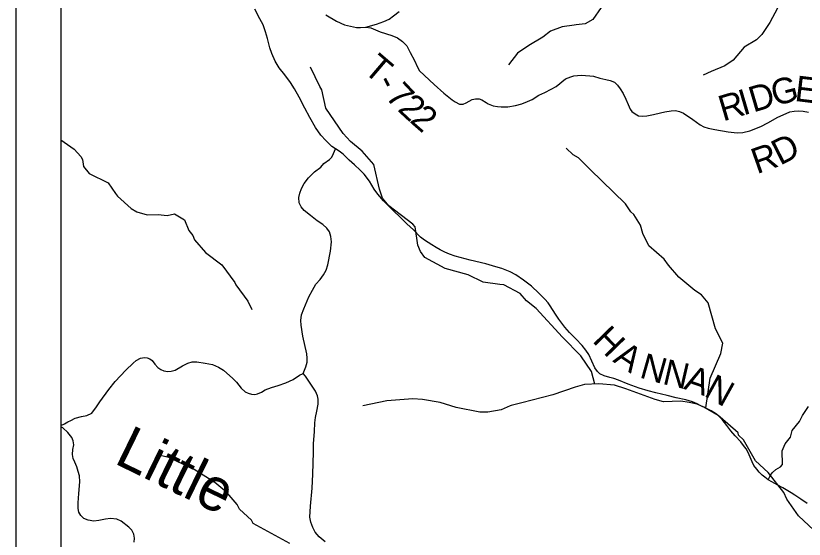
# Model space of a CAD drawing. Extents: x -1.8 to 75.7, y -2 to 25.
# Drawn here: x 2 to 3.751, y 17.804 to 18.965 of the extents above; entities that cross this region are included whole.
import ezdxf

# ---------------------------------------------------------------- set-up
doc = ezdxf.new("R2010")
doc.units = 0
for name, color, linetype in [('GM_X_County_Road', 7, 'Continuous'), ('GM_X_County_Road_Text', 7, 'Continuous'), ('GM_X_Minor_River', 7, 'Continuous'), ('GM_X_Minor_River_Text', 7, 'Continuous'), ('GM_X_Township', 7, 'Continuous'), ('GM_X_Township_Road', 7, 'Continuous'), ('GM_X_Township_Road_Text', 7, 'Continuous'), ('GM_X_Township_ROW', 7, 'Continuous'), ('SH_Data', 7, 'Continuous')]:
    doc.layers.add(name, color=color, linetype=linetype)

msp = doc.modelspace()

# ---------------------------------------------------------------- linework, layer by layer
at = {"layer": 'GM_X_County_Road'}
for points in [[(3.7576, 17.8828), (3.7429, 17.8927), (3.7296, 17.9015), (3.7215, 17.9065), (3.7147, 17.9108), (3.7034, 17.918), (3.6921, 17.9239), (3.6786, 17.9307), (3.6704, 17.9357), (3.663, 17.9413), (3.6571, 17.946), (3.6508, 17.9526), (3.6454, 17.9587), (3.639, 17.9675), (3.635, 17.9756), (3.6286, 17.9908), (3.6255, 17.9978), (3.6219, 18.0041), (3.6162, 18.0116), (3.6097, 18.0199), (3.5977, 18.0332), (3.588, 18.0445), (3.5792, 18.0561), (3.5688, 18.0692), (3.5604, 18.0771), (3.5539, 18.0823), (3.5442, 18.0884), (3.5326, 18.0942), (3.5213, 18.0999), (3.5128, 18.1044), (3.5024, 18.1087), (3.4875, 18.113), (3.4662, 18.1177), (3.4461, 18.1222), (3.4213, 18.1283), (3.4041, 18.1329), (3.384, 18.139), (3.3598, 18.148), (3.3384, 18.1566), (3.328, 18.1604), (3.3194, 18.1625), (3.3065, 18.1663), (3.2972, 18.1706), (3.2918, 18.1756), (3.286, 18.1837), (3.2789, 18.1991), (3.2724, 18.2133), (3.2661, 18.223), (3.2575, 18.2336), (3.2437, 18.2485), (3.2297, 18.2625), (3.2191, 18.2743), (3.2123, 18.2831), (3.2058, 18.2919), (3.1988, 18.3034), (3.1868, 18.3217), (3.1823, 18.3283), (3.175, 18.3366), (3.1615, 18.3497), (3.145, 18.3649), (3.1276, 18.3784), (3.1104, 18.3902), (3.0978, 18.3969), (3.079, 18.4044), (3.0662, 18.4082), (3.044, 18.4148), (3.009, 18.4231), (2.9756, 18.432), (2.9629, 18.4362), (2.9528, 18.4408), (2.9426, 18.4457), (2.9336, 18.4509), (2.9236, 18.4568), (2.9076, 18.4674), (2.8985, 18.4742), (2.8832, 18.4902), (2.8687, 18.5038), (2.8547, 18.517), (2.8375, 18.5336), (2.8168, 18.5544), (2.8043, 18.5693), (2.7959, 18.5803), (2.7854, 18.5981), (2.7735, 18.6138), (2.7645, 18.6229), (2.7518, 18.6345), (2.7406, 18.6446), (2.7268, 18.658), (2.7182, 18.6651), (2.7098, 18.67), (2.7019, 18.6754), (2.6888, 18.6881), (2.6771, 18.7006), (2.6653, 18.7174), (2.6526, 18.7397), (2.6418, 18.76), (2.6291, 18.7849), (2.619, 18.8028), (2.61, 18.817), (2.5971, 18.8342), (2.5848, 18.8499), (2.5758, 18.8648), (2.5685, 18.8816), (2.5641, 18.8938), (2.5588, 18.9147), (2.5547, 18.9295), (2.5491, 18.945), (2.5422, 18.9588), (2.5306, 18.9797)], [(2.6883, 18.9676), (2.712, 18.9536), (2.7302, 18.9451), (2.7432, 18.9418), (2.7569, 18.9395), (2.7654, 18.9392), (2.7775, 18.9401), (2.801, 18.9467), (2.8176, 18.9526), (2.8291, 18.9574), (2.8388, 18.9649), (2.8516, 18.9746)]]:
    msp.add_lwpolyline(points, dxfattribs=at)
at = {"layer": 'GM_X_Minor_River'}
for points in [[(3.4876, 19.2435), (3.4826, 19.241), (3.4682, 19.2168), (3.4642, 19.1831), (3.4509, 19.1668), (3.428, 19.1607), (3.4004, 19.1365), (3.3858, 19.1138), (3.3742, 19.1062), (3.3531, 19.0963), (3.3264, 19.0394), (3.3226, 19.0236), (3.318, 19.0108), (3.2812, 18.9573), (3.2647, 18.9472), (3.2446, 18.9448), (3.2396, 18.9442), (3.2131, 18.9404), (3.1875, 18.9314), (3.1704, 18.9175), (3.1389, 18.8995), (3.1138, 18.8821), (3.0941, 18.8561)], [(3.7086, 19.0147), (3.6745, 18.9504), (3.6567, 18.9237), (3.645, 18.9119), (3.6173, 18.8957), (3.5926, 18.8668), (3.5741, 18.8545), (3.5442, 18.8418), (3.5266, 18.8336)], [(3.2861, 18.1476), (3.2787, 18.1759), (3.2548, 18.2108), (3.2137, 18.252), (3.1552, 18.3158), (3.1337, 18.3328), (3.1203, 18.3492), (3.0834, 18.3682), (3.0747, 18.3689), (3.0375, 18.3742), (3.0043, 18.3905), (2.9537, 18.4042), (2.9083, 18.4289), (2.8985, 18.4421), (2.8929, 18.4559), (2.8866, 18.4968), (2.8815, 18.5026), (2.8283, 18.5434), (2.8144, 18.5602), (2.8075, 18.5802), (2.7948, 18.6349), (2.7692, 18.665), (2.7434, 18.6863), (2.7269, 18.7039), (2.6882, 18.7602), (2.6796, 18.8007), (2.6749, 18.8081), (2.6546, 18.8513)], [(2.1, 18.6899), (2.1295, 18.6689), (2.1445, 18.6532), (2.1485, 18.6462), (2.1503, 18.631), (2.163, 18.615), (2.2051, 18.5947), (2.2218, 18.5706), (2.2261, 18.5652), (2.2563, 18.5376), (2.2686, 18.5304), (2.2918, 18.5232), (2.316, 18.5239), (2.336, 18.5218), (2.3523, 18.5254), (2.375, 18.5122), (2.3845, 18.4887), (2.3928, 18.4774), (2.3971, 18.4678), (2.4212, 18.4401), (2.4574, 18.4123), (2.4864, 18.373), (2.4889, 18.368), (2.5151, 18.3322), (2.5242, 18.3133)], [(3.5325, 18.095), (3.5417, 18.1612), (3.5657, 18.2155), (3.5701, 18.2389), (3.5537, 18.2702), (3.5373, 18.328), (3.5227, 18.3463), (3.5079, 18.3552), (3.4725, 18.3848), (3.4495, 18.4121), (3.4397, 18.4253), (3.4058, 18.4549), (3.3927, 18.4819), (3.3872, 18.5007), (3.3724, 18.5239), (3.3661, 18.5298), (3.3542, 18.5477), (3.2752, 18.6242), (3.2496, 18.6501), (3.238, 18.6566), (3.2222, 18.6711)], [(3.7719, 17.8234), (3.7382, 17.8557), (3.7121, 17.8928), (3.7053, 17.9073), (3.6708, 17.9513), (3.6428, 17.9774), (3.6334, 17.993), (3.6159, 18.0241), (3.605, 18.0347), (3.6038, 18.0397), (3.5641, 18.0746), (3.5596, 18.078), (3.5282, 18.0969), (3.5134, 18.1033), (3.4956, 18.1067), (3.4767, 18.1097), (3.4386, 18.1088), (3.4197, 18.1137), (3.3546, 18.1372), (3.3293, 18.1455), (3.2945, 18.1488), (3.2627, 18.1468), (3.242, 18.1411), (3.1928, 18.1242), (3.1236, 18.1061)], [(3.1239, 18.1061), (3.1002, 18.1004), (3.0976, 18.0997), (3.0776, 18.0905), (3.0481, 18.0859), (3.0307, 18.0854), (2.9782, 18.0956), (2.9422, 18.1069), (2.9029, 18.1136), (2.8814, 18.1151), (2.8243, 18.1104), (2.7706, 18.0996)], [(2.6088, 17.7943), (2.5274, 17.8382), (2.5233, 17.8458), (2.4968, 17.8701), (2.4919, 17.8807), (2.4692, 17.9065), (2.4639, 17.9107), (2.4419, 17.9297), (2.3961, 17.9584), (2.3402, 17.9853), (2.3209, 17.9894), (2.3209, 17.9891)]]:
    msp.add_lwpolyline(points, dxfattribs=at)
at = {"layer": 'GM_X_Township'}
msp.add_lwpolyline([(6.4874, 20.9), (2.1, 20.9), (2.1, 17.3659)], dxfattribs=at)
at = {"layer": 'GM_X_Township_Road'}
for points in [[(2.7775, 18.9401), (2.7884, 18.9381), (2.8092, 18.9297), (2.8351, 18.9212), (2.8475, 18.9162), (2.8587, 18.908), (2.868, 18.8982), (2.8761, 18.8838), (2.8854, 18.8658), (2.8924, 18.8509), (2.8967, 18.8434), (2.929, 18.813), (2.9506, 18.7936), (2.9687, 18.7786), (2.9758, 18.7741), (2.9853, 18.7694), (2.9931, 18.7692), (3.0001, 18.7718), (3.0136, 18.7792), (3.0208, 18.781), (3.0288, 18.7807), (3.035, 18.7786), (3.0444, 18.773), (3.0493, 18.7698), (3.0602, 18.7656), (3.07, 18.7638), (3.0778, 18.7632), (3.0927, 18.7632), (3.1098, 18.7662), (3.1235, 18.7701), (3.1361, 18.7747), (3.1464, 18.7795), (3.1617, 18.7889), (3.1746, 18.7953), (3.1889, 18.8021), (3.1998, 18.8085), (3.2208, 18.8252), (3.2323, 18.8297), (3.2394, 18.8318), (3.2552, 18.8331), (3.2744, 18.832), (3.2827, 18.831), (3.2969, 18.8271), (3.3105, 18.8235), (3.3202, 18.8214), (3.3292, 18.8179), (3.336, 18.8115), (3.3424, 18.8034), (3.3486, 18.7925), (3.3544, 18.7805), (3.3599, 18.7686), (3.364, 18.7581), (3.3683, 18.7531), (3.3753, 18.7474), (3.383, 18.7435), (3.3907, 18.7425), (3.401, 18.7431), (3.416, 18.7465), (3.4316, 18.7499), (3.4416, 18.7523), (3.4555, 18.7542), (3.4647, 18.7547), (3.4739, 18.7531), (3.4829, 18.7489), (3.5034, 18.735), (3.5196, 18.7232), (3.5282, 18.7185), (3.5376, 18.7157), (3.5522, 18.7128), (3.5821, 18.708), (3.602, 18.7055), (3.6141, 18.7065), (3.6298, 18.7097), (3.6546, 18.7196), (3.6702, 18.7279), (3.6924, 18.7401), (3.7108, 18.7487), (3.7191, 18.7519), (3.7287, 18.7538), (3.7382, 18.754), (3.7482, 18.7532), (3.76, 18.751)], [(2.1, 18.056), (2.1079, 18.0595), (2.1154, 18.0644), (2.1221, 18.0672), (2.1316, 18.0722), (2.1462, 18.076), (2.1576, 18.0784), (2.1688, 18.0834), (2.1796, 18.0973), (2.1867, 18.1085), (2.2063, 18.1361), (2.2207, 18.1539), (2.2441, 18.1785), (2.2605, 18.1944), (2.2676, 18.2004), (2.2771, 18.2054), (2.2855, 18.2069), (2.2917, 18.206), (2.2979, 18.2039), (2.3027, 18.2), (2.3091, 18.1918), (2.3154, 18.1849), (2.322, 18.18), (2.3289, 18.1776), (2.338, 18.1759), (2.3451, 18.1763), (2.3543, 18.1785), (2.3705, 18.1882), (2.3819, 18.1946), (2.3918, 18.197), (2.4019, 18.1976), (2.4202, 18.1946), (2.4365, 18.1914), (2.4499, 18.1856), (2.4613, 18.1785), (2.4822, 18.1604), (2.4901, 18.152), (2.5007, 18.1389), (2.5095, 18.1307), (2.5157, 18.1277), (2.5235, 18.1253), (2.5308, 18.1249), (2.537, 18.126), (2.5454, 18.1296), (2.5538, 18.135), (2.568, 18.1402), (2.5827, 18.1447), (2.5999, 18.1505), (2.616, 18.1583), (2.63, 18.1675), (2.6384, 18.1714), (2.6438, 18.1858), (2.6468, 18.1966), (2.647, 18.2054), (2.6461, 18.2151), (2.6373, 18.2544), (2.6334, 18.2788), (2.6332, 18.2891), (2.6347, 18.3014), (2.6395, 18.3147), (2.6511, 18.3414), (2.6586, 18.356), (2.6662, 18.3698), (2.6756, 18.3803), (2.6832, 18.3902), (2.6892, 18.401), (2.6933, 18.4128), (2.6987, 18.443), (2.7008, 18.4632), (2.6997, 18.4755), (2.6965, 18.4856), (2.6909, 18.494), (2.6821, 18.5019), (2.6692, 18.5105), (2.6547, 18.5217), (2.6405, 18.5329), (2.6337, 18.5413), (2.6296, 18.5499), (2.6287, 18.5618), (2.6304, 18.5717), (2.6347, 18.582), (2.6403, 18.5927), (2.6502, 18.6054), (2.6634, 18.6186), (2.6771, 18.6295), (2.6844, 18.6371), (2.6963, 18.6465), (2.7019, 18.6515), (2.7058, 18.6599), (2.7098, 18.67)], [(2.6871, 17.7975), (2.6734, 17.8086), (2.6649, 17.8195), (2.6598, 17.8297), (2.6551, 17.8412), (2.6533, 17.8524), (2.6545, 17.8771), (2.658, 17.9168), (2.6594, 17.9482), (2.6612, 17.9966), (2.6614, 18.0156), (2.6631, 18.0429), (2.6642, 18.0621), (2.6659, 18.0739), (2.6687, 18.0877), (2.6713, 18.1034), (2.6717, 18.1143), (2.67, 18.1219), (2.6655, 18.1318), (2.6433, 18.1656), (2.6384, 18.1714)], [(2.2628, 17.797), (2.2635, 17.806), (2.2621, 17.8151), (2.2577, 17.8237), (2.2512, 17.8304), (2.2339, 17.8434), (2.2243, 17.8481), (2.2104, 17.8497), (2.1996, 17.8481), (2.1848, 17.8452), (2.1732, 17.8438), (2.1604, 17.8456), (2.151, 17.8499), (2.1443, 17.8562), (2.1398, 17.8635), (2.1384, 17.8718), (2.1382, 17.8844), (2.14, 17.9048), (2.1422, 17.9312), (2.1414, 17.9442), (2.1389, 17.9541), (2.1357, 17.9646), (2.1308, 17.9745), (2.1275, 17.983), (2.1257, 17.9915), (2.127, 18.0025), (2.129, 18.0133), (2.1277, 18.022), (2.1243, 18.0294), (2.1158, 18.0401), (2.1046, 18.0507), (2.1, 18.0531)]]:
    msp.add_lwpolyline(points, dxfattribs=at)
at = {"layer": 'GM_X_Township_ROW'}
msp.add_lwpolyline([(3.6704, 17.9357), (3.6756, 17.9456), (3.68, 17.9517), (3.6875, 17.958), (3.6983, 17.9645), (3.7025, 17.9696), (3.7027, 17.9809), (3.702, 17.9879), (3.702, 17.9999), (3.7088, 18.0156), (3.7206, 18.0303), (3.7243, 18.0446), (3.7401, 18.065), (3.747, 18.0783), (3.7601, 18.0979)], dxfattribs=at)
at = {"layer": 'SH_Data'}
for p, q in [((2, 21), (2, 14)), ((2.1, 20.9), (2.1, 14.1))]:
    msp.add_line(p, q, dxfattribs=at)

# ---------------------------------------------------------------- texts
at = {"layer": 'GM_X_County_Road_Text'}
for s, rotation, p in [('H', 314.1525, (3.2787, 18.2429)), ('A', 326.6004, (3.3239, 18.1985)), ('N', 344.1566, (3.3829, 18.163)), ('N', 347.0117, (3.434, 18.1486)), ('A', 340.8618, (3.4812, 18.1378)), ('N', 330.9905, (3.526, 18.1225))]:
    msp.add_text(s, height=0.0568, rotation=rotation, dxfattribs=at).set_placement(p)
at = {"layer": 'GM_X_Minor_River_Text'}
msp.add_text('Little', height=0.0947, rotation=333.998, dxfattribs=at).set_placement((2.2157, 17.9734))
at = {"layer": 'GM_X_Township_Road_Text'}
for s, rotation, p in [('T', 319.5365, (2.7697, 18.842)), ('-', 297.4099, (2.7984, 18.819)), ('G', 14.2872, (3.685, 18.7645)), ('E', 353.0467, (3.7279, 18.7765)), ('7', 313.1101, (2.8189, 18.7844)), ('D', 16.4693, (3.6376, 18.7504)), ('2', 317.0527, (2.8459, 18.7559)), ('R', 16.482, (3.5705, 18.7306)), ('I', 16.4878, (3.6152, 18.7438)), ('2', 318.7527, (2.8728, 18.7308)), ('D', 27.0523, (3.6971, 18.6322)), ('R', 19.3915, (3.6456, 18.6135))]:
    msp.add_text(s, height=0.0568, rotation=rotation, dxfattribs=at).set_placement(p)

doc.saveas('drawing.dxf')
